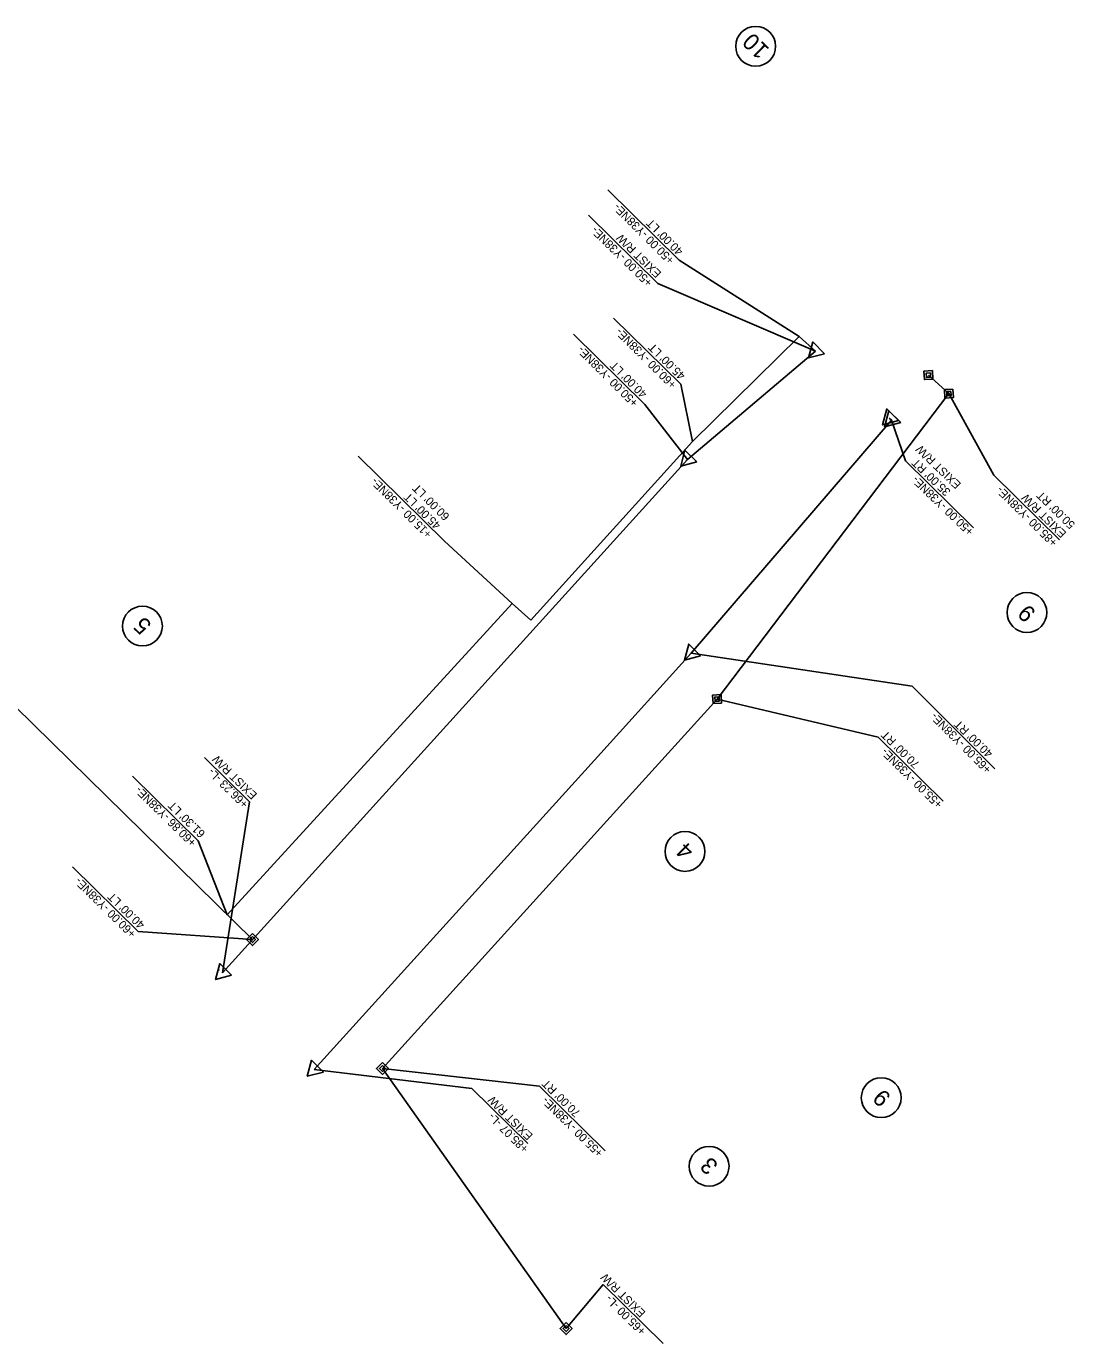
# Model space of a CAD drawing. Extents: x 1266020 to 1268272, y 771352 to 772865.
# Drawn here: x 1266724 to 1267355, y 772072 to 772865 of the extents above; entities that cross this region are included whole.
import ezdxf

# ---------------------------------------------------------------- set-up
doc = ezdxf.new("R2010")
doc.units = 0
for name, color, linetype in [('Prop Easement Construction', 7, 'Continuous'), ('Prop Easement Construction Station Offsets', 7, 'Continuous'), ('Prop Easement Permanent Utility', 7, 'Continuous'), ('Prop Easement Permanent Utility Station Offsets', 7, 'Continuous'), ('Prop Parcel Number CELL', 7, 'Continuous'), ('Prop Parcel Number Text', 7, 'Continuous'), ('Prop ROW Marker CELL', 7, 'Continuous'), ('Prop ROW Permanent Easement CELL', 7, 'Continuous'), ('Prop ROW RW Lines', 7, 'Continuous'), ('Prop ROW Station Offsets', 7, 'Continuous')]:
    doc.layers.add(name, color=color, linetype=linetype)

msp = doc.modelspace()

# ---------------------------------------------------------------- linework, layer by layer
at = {"layer": 'Prop Easement Construction'}
for p, q in [((1267124.8, 772614.84), (1267027.47, 772507.36)), ((1267016.35, 772517.42), (1266844.8, 772329.91)), ((1267016.35, 772517.42), (1267027.47, 772507.36)), ((1266840.06, 772296.67), (1266839.92, 772296.53))]:
    msp.add_line(p, q, dxfattribs=at)
msp.add_lwpolyline([(1267124.8, 772614.84), (1267188.92, 772678.19), (1267198.77, 772669.27)], dxfattribs=at)
at = {"layer": 'Prop Easement Construction Station Offsets'}
for p, q in [((1267116.85, 772724.05), (1267073.79, 772766.48)), ((1267116.85, 772724.05), (1267188.92, 772678.19)), ((1267077.34, 772689.26), (1267117.77, 772649.42)), ((1267117.77, 772649.42), (1267124.8, 772614.84)), ((1266923.64, 772606.1), (1266975.53, 772554.97)), ((1266975.53, 772554.97), (1267016.35, 772517.42)), ((1266787.76, 772413.42), (1266827.28, 772374.49)), ((1266827.28, 772374.49), (1266844.8, 772329.91))]:
    msp.add_line(p, q, dxfattribs=at)
at = {"layer": 'Prop Easement Permanent Utility'}
for p, q in [((1267266.78, 772654.9), (1267279.12, 772643.73)), ((1267279.12, 772643.73), (1267139.56, 772459.81)), ((1266860.01, 772314.98), (1266550.91, 772618.41)), ((1267094.46, 772410.01), (1267139.56, 772459.81)), ((1267094.46, 772410.01), (1266938.19, 772237.44)), ((1267048.76, 772080.75), (1266938.19, 772237.44))]:
    msp.add_line(p, q, dxfattribs=at)
at = {"layer": 'Prop Easement Permanent Utility Station Offsets'}
for p, q in [((1267306.11, 772594.55), (1267345.59, 772555.65)), ((1267275.61, 772398.33), (1267236.61, 772436.81)), ((1266751.71, 772358.83), (1266791.22, 772319.9)), ((1267032.77, 772226.65), (1266938.19, 772237.44)), ((1267032.77, 772226.65), (1267072.29, 772187.71)), ((1267070.99, 772107.35), (1267107.2, 772071.67))]:
    msp.add_line(p, q, dxfattribs=at)
for points in [[(1267306.11, 772594.55), (1267279.12, 772643.73)], [(1267236.61, 772436.81), (1267139.56, 772459.81)], [(1266791.22, 772319.9), (1266860.01, 772314.98)], [(1267070.99, 772107.35), (1267048.76, 772080.75)]]:
    msp.add_lwpolyline(points, dxfattribs=at)
at = {"layer": 'Prop Parcel Number CELL'}
for p, q in [((1267162.81, 772852.89), (1267162.81, 772852.89)), ((1267326.07, 772511.93), (1267326.07, 772511.93)), ((1266793.79, 772503.79), (1266793.79, 772503.79)), ((1267120.29, 772368.06), (1267120.29, 772368.06)), ((1267238.38, 772219.78), (1267238.38, 772219.78)), ((1267134.81, 772178.47), (1267134.81, 772178.47))]:
    msp.add_line(p, q, dxfattribs=at)
for centre in [(1267162.81, 772852.89), (1267326.07, 772511.93), (1266793.79, 772503.79), (1267120.29, 772368.06), (1267238.38, 772219.78), (1267134.81, 772178.47)]:
    msp.add_circle(centre, 12, dxfattribs=at)
at = {"layer": 'Prop ROW Marker CELL'}
for p, q in [((1267198.77, 772669.27), (1267198.77, 772669.27)), ((1267243.24, 772629), (1267243.24, 772629)), ((1267244.51, 772627.85), (1267244.51, 772627.85)), ((1267121.79, 772604.07), (1267121.79, 772604.07)), ((1267124.04, 772487.36), (1267124.04, 772487.36)), ((1266841.9, 772294.98), (1266841.9, 772294.98)), ((1266897.07, 772236.73), (1266897.07, 772236.73))]:
    msp.add_line(p, q, dxfattribs=at)
for points in [[(1267204.34, 772667.77), (1267194.69, 772665.2), (1267197.27, 772674.84)], [(1267248.81, 772627.5), (1267239.17, 772624.93), (1267241.74, 772634.57)], [(1267250.08, 772626.35), (1267240.44, 772623.78), (1267243.01, 772633.42)], [(1267127.36, 772602.57), (1267117.72, 772600), (1267120.29, 772609.64)], [(1267129.61, 772485.86), (1267119.96, 772483.29), (1267122.54, 772492.94)], [(1266847.47, 772293.48), (1266837.82, 772290.9), (1266840.4, 772300.55)], [(1266902.65, 772235.23), (1266893, 772232.65), (1266895.58, 772242.3)]]:
    msp.add_lwpolyline(points, close=True, dxfattribs=at)
at = {"layer": 'Prop ROW Permanent Easement CELL'}
for p, q in [((1267266.78, 772654.9), (1267266.78, 772654.9)), ((1267279.12, 772643.73), (1267279.12, 772643.73)), ((1267139.56, 772459.81), (1267139.56, 772459.81)), ((1266860.01, 772314.98), (1266860.01, 772314.98)), ((1266938.19, 772237.44), (1266938.19, 772237.44)), ((1267048.76, 772080.75), (1267048.76, 772080.75))]:
    msp.add_line(p, q, dxfattribs=at)
for points in [[(1267269.19, 772657.57), (1267269.45, 772652.49), (1267264.36, 772652.24), (1267264.11, 772657.32)], [(1267267.99, 772656.24), (1267268.11, 772653.69), (1267265.57, 772653.57), (1267265.44, 772656.11)], [(1267281.54, 772646.39), (1267281.79, 772641.31), (1267276.7, 772641.06), (1267276.45, 772646.14)], [(1267280.33, 772645.06), (1267280.45, 772642.52), (1267277.91, 772642.39), (1267277.79, 772644.93)], [(1267141.98, 772462.48), (1267142.23, 772457.4), (1267137.15, 772457.15), (1267136.89, 772462.23)], [(1267140.77, 772461.15), (1267140.9, 772458.61), (1267138.35, 772458.48), (1267138.23, 772461.02)], [(1266860.01, 772318.58), (1266863.61, 772314.98), (1266860.01, 772311.38), (1266856.41, 772314.98)], [(1266860.01, 772316.78), (1266861.81, 772314.98), (1266860.01, 772313.18), (1266858.21, 772314.98)], [(1266938.19, 772241.04), (1266941.79, 772237.44), (1266938.19, 772233.84), (1266934.59, 772237.44)], [(1266938.19, 772239.24), (1266939.99, 772237.44), (1266938.19, 772235.64), (1266936.39, 772237.44)], [(1267048.76, 772084.35), (1267052.36, 772080.75), (1267048.76, 772077.15), (1267045.16, 772080.75)], [(1267048.76, 772082.55), (1267050.56, 772080.75), (1267048.76, 772078.95), (1267046.96, 772080.75)]]:
    msp.add_lwpolyline(points, close=True, dxfattribs=at)
at = {"layer": 'Prop ROW RW Lines'}
for p, q in [((1267021.11, 772492.88), (1266841.9, 772294.98)), ((1267124.04, 772487.36), (1267069.64, 772427.29)), ((1267069.64, 772427.29), (1266897.07, 772236.73)), ((1267069.64, 772427.29), (1267069.64, 772427.29))]:
    msp.add_line(p, q, dxfattribs=at)
for points in [[(1267198.77, 772669.27), (1267121.79, 772604.07)], [(1267243.24, 772629), (1267244.51, 772627.85), (1267124.04, 772487.36)], [(1267121.79, 772604.07), (1267021.11, 772492.88)]]:
    msp.add_lwpolyline(points, dxfattribs=at)
at = {"layer": 'Prop ROW Station Offsets'}
for p, q in [((1267103.98, 772710), (1267062.18, 772751.13)), ((1267103.98, 772710), (1267198.77, 772669.27)), ((1267053.14, 772679.57), (1267096.15, 772637.19)), ((1267096.15, 772637.19), (1267121.79, 772604.07)), ((1267253, 772603.22), (1267293.96, 772562.93)), ((1267257.09, 772467.53), (1267124.04, 772487.36)), ((1267257.09, 772467.53), (1267306.81, 772417.87)), ((1266831.16, 772424.67), (1266858.24, 772397.99)), ((1266858.24, 772397.99), (1266841.9, 772294.98)), ((1266992.09, 772225.22), (1266897.07, 772236.73)), ((1266992.09, 772225.22), (1267025.68, 772192.13))]:
    msp.add_line(p, q, dxfattribs=at)
msp.add_lwpolyline([(1267253, 772603.22), (1267244.51, 772627.85)], dxfattribs=at)

# ---------------------------------------------------------------- texts
at = {"layer": 'Prop Easement Construction Station Offsets'}
for s, rotation, p in [('+50.00 -Y38NE-', 135.03073, (1267114.27, 772724.61)), ("40.00' LT", 135.03073, (1267119.57, 772729.91)), ('+60.00 -Y38NE-', 135.08702, (1267115.57, 772649.68)), ("45.00' LT", 135.08702, (1267120.87, 772654.99)), ('+15.00 -Y38NE-', 135.18524, (1266968.44, 772559.63)), ("60.00' LT", 135.18524, (1266979.01, 772570.27)), ("45.00' LT", 135.18524, (1266973.73, 772564.95)), ('+60.86 -Y38NE-', 135.42387, (1266826.64, 772373.92)), ("61.30' LT", 135.42387, (1266831.91, 772379.26))]:
    msp.add_text(s, height=5, rotation=rotation, dxfattribs=at).set_placement(p)
at = {"layer": 'Prop Easement Permanent Utility Station Offsets'}
for s, rotation, p in [('+85.00 -Y38NE-', 135.42387, (1267344.89, 772554.59)), ('EXIST R/W', 135.42387, (1267350.15, 772559.93)), ("50.00' RT", 135.42387, (1267355.42, 772565.28)), ("70.00' RT", 135.50192, (1267261.88, 772421.03)), ('+55.00 -Y38NE-', 135.50192, (1267275.61, 772397.03)), ('+60.00 -Y38NE-', 135.42387, (1266790.31, 772319.05)), ("40.00' LT", 135.42387, (1266795.58, 772324.39)), ("70.00' RT", 135.42387, (1267057.73, 772211.01)), ('+55.00 -Y38NE-', 135.42387, (1267071.43, 772186.98)), ('EXIST R/W', 135.42387, (1267096.96, 772090.54)), ('+65.00 -L-', 135.42387, (1267097.16, 772079.81))]:
    msp.add_text(s, height=5, rotation=rotation, dxfattribs=at).set_placement(p)
at = {"layer": 'Prop Parcel Number Text'}
for s, p in [('10', (1267171.61, 772851.24)), ('5', (1266799.87, 772504.83)), ('9', (1267332, 772512.26)), ('4', (1267126.32, 772369.13)), ('9', (1267244.8, 772220.46)), ('3', (1267140.86, 772179.53))]:
    msp.add_text(s, height=10, rotation=135.42387, dxfattribs=at).set_placement(p)
at = {"layer": 'Prop ROW Station Offsets'}
for s, rotation, p in [('+50.00 -Y38NE-', 135.61711, (1267101.17, 772711.14)), ('EXIST R/W', 135.61711, (1267106.42, 772716.5)), ('+50.00 -Y38NE-', 134.95662, (1267092.51, 772638.74)), ("40.00' LT", 134.95662, (1267097.82, 772644.04)), ('EXIST R/W', 136.04686, (1267286.77, 772589.45)), ("35.00' RT", 136.04686, (1267280.48, 772585.09)), ('+50.00 -Y38NE-', 136.04686, (1267294.44, 772561.21)), ('+65.00 -Y38NE-', 134.93623, (1267305.07, 772417.95)), ("40.00' RT", 135.85461, (1267305.89, 772427.55)), ('EXIST R/W', 135.42387, (1266863.15, 772402.46)), ('+66.23 -L-', 135.42387, (1266857.89, 772397.12)), ('EXIST R/W', 135.42387, (1267029.06, 772197.3)), ('+85.07 -L-', 135.42387, (1267026.57, 772189.57))]:
    msp.add_text(s, height=5, rotation=rotation, dxfattribs=at).set_placement(p)

doc.saveas('drawing.dxf')
